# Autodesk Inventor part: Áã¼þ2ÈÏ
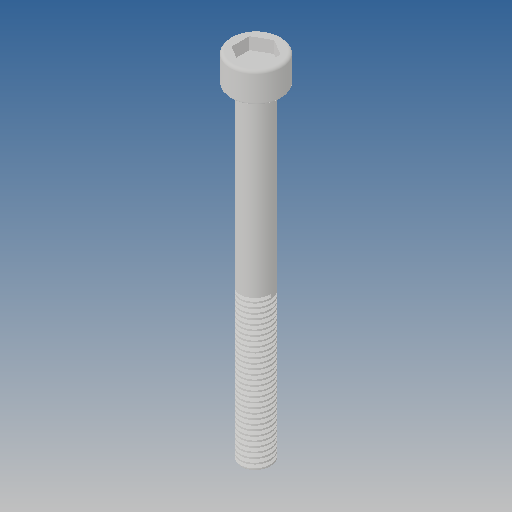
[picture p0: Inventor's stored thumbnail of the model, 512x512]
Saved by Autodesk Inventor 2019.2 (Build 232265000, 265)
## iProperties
Created: 2013-07
Part Number: Áã¼þ2ÈÏ
Material: Ogólny
Document SubType Name: Modeling
Designer: CADENGINEERING4
Density: 1 g/cm^3
Appearance: Domyślna
Author: CADENGINEERING4
Revision Number: ÈÎºÎ
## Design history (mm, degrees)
feature "ÇÐ³ý-É¨Ãè1"
node "Bryła1"
